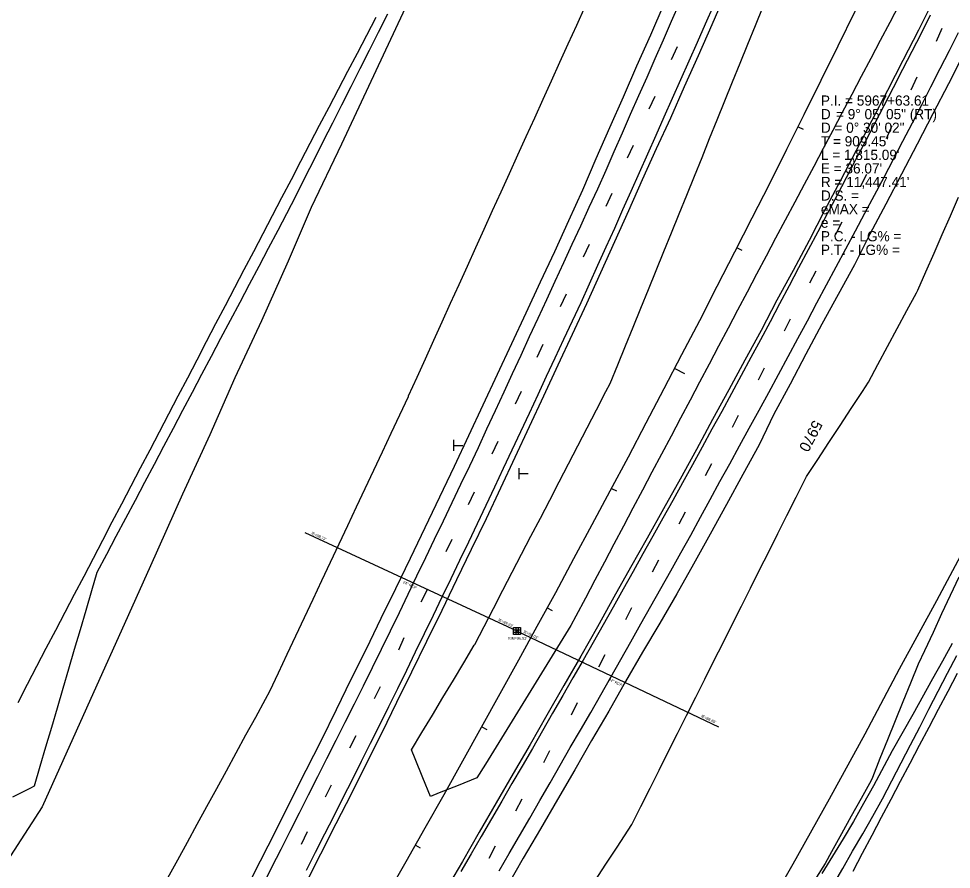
# Model space of a CAD drawing. Extents: x 2132221 to 2141942, y 535736 to 547298.
# Drawn here: x 2139563 to 2140250, y 543611 to 544238 of the extents above; entities that cross this region are included whole.
import ezdxf

# ---------------------------------------------------------------- set-up
doc = ezdxf.new("R2010")
doc.units = 0
for name, color, linetype in [('RD_EX_BldgApp', 7, 'Continuous'), ('RD_EX_DR_Inlet', 7, 'Continuous'), ('RD_EX_DR_Inlet_txCode', 7, 'Continuous'), ('RD_EX_DR_Pipe', 7, 'Continuous'), ('RD_EX_DR_Pipe_txCode', 7, 'Continuous'), ('RD_EX_Driveway', 7, 'Continuous'), ('RD_EX_Fence_Other', 7, 'Continuous'), ('RD_EX_Misc', 7, 'Continuous'), ('RD_EX_Road', 7, 'Continuous'), ('RD_EX_VEG', 7, 'Continuous'), ('RD_HC_Cl', 7, 'Continuous'), ('RD_HC_Data', 7, 'Continuous'), ('RD_HC_Data_Tic', 7, 'Continuous'), ('RD_HC_TX_Sta50', 7, 'Continuous'), ('TOPO_E_TLIML-Line', 7, 'Continuous')]:
    doc.layers.add(name, color=color, linetype=linetype)

msp = doc.modelspace()

# ---------------------------------------------------------------- linework, layer by layer
at = {"layer": 'RD_EX_BldgApp'}
for p, q in [((2139883.31, 543927.7), (2139883.31, 543923.58)), ((2139883.31, 543923.58), (2139883.31, 543919.47)), ((2139883.31, 543923.58), (2139890.17, 543923.58)), ((2139931.41, 543906.84), (2139931.41, 543902.72)), ((2139931.41, 543902.72), (2139931.41, 543898.6)), ((2139931.41, 543902.72), (2139938.27, 543902.72))]:
    msp.add_line(p, q, dxfattribs=at)
at = {"layer": 'RD_EX_DR_Inlet'}
for p, q in [((2139929.25, 543789.24), (2139929.25, 543784.24)), ((2139930.95, 543789.24), (2139930.95, 543784.24)), ((2139927.55, 543787.54), (2139932.55, 543787.54)), ((2139927.55, 543785.84), (2139932.55, 543785.84))]:
    msp.add_line(p, q, dxfattribs=at)
msp.add_lwpolyline([(2139927.55, 543784.24), (2139927.55, 543789.24), (2139932.55, 543789.24), (2139932.55, 543784.24)], close=True, dxfattribs=at)
at = {"layer": 'RD_EX_DR_Pipe'}
for q in [(2139773.88, 543859.09), (2140078.46, 543716.15)]:
    msp.add_line((2139930.09, 543786.68), q, dxfattribs=at)
at = {"layer": 'RD_EX_Driveway'}
for points in [[(2140250.79, 543777.62), (2140243.52, 543764.49), (2140236.26, 543751.36), (2140221.74, 543725.11), (2140206.45, 543698.27), (2140192.7, 543672.61), (2140185.44, 543659.49), (2140178.11, 543646.4), (2140170.32, 543633.58), (2140162.52, 543620.77), (2140154.73, 543607.95)], [(2140162.59, 543598.61), (2140170.07, 543611.61), (2140177.42, 543624.37), (2140184.84, 543637.25), (2140192.25, 543650.14), (2140199.53, 543663.1), (2140206.35, 543676.3), (2140213.17, 543689.51), (2140220, 543702.72), (2140226.82, 543715.92), (2140233.64, 543729.13), (2140240.47, 543742.34), (2140247.29, 543755.54), (2140254.11, 543768.75)]]:
    msp.add_lwpolyline(points, dxfattribs=at)
at = {"layer": 'RD_EX_Fence_Other'}
for points in [[(2140036.9, 544651.45), (2140013.35, 544603.46), (2139990.72, 544555.01), (2139970.35, 544511.31), (2139951.33, 544470.75), (2139928.94, 544422.41), (2139907.73, 544376.6), (2139887.27, 544332.67), (2139866.93, 544288.8), (2139845.9, 544242.19), (2139800.8, 544145.6), (2139778.31, 544098.97), (2139761.47, 544059.46), (2139741.78, 544015.43), (2139722.06, 543973.25), (2139703.54, 543931.28), (2139683.53, 543887.51), (2139659.89, 543834.83), (2139638.39, 543786.68), (2139620.42, 543746.85), (2139579.95, 543657.2), (2139556.74, 543620.94)], [(2139769.46, 542989.44), (2139792.81, 543030.29), (2139817.84, 543075.19), (2139841.76, 543117.2), (2139858.83, 543147.31), (2139881.84, 543188.22), (2139920.2, 543256.34), (2139947.4, 543301.84), (2139972.72, 543344.13), (2139997.22, 543384.87), (2140028.43, 543436.8), (2140054.25, 543479.64), (2140085.07, 543531.26), (2140112.36, 543577.99), (2140133.52, 543615.15), (2140160.47, 543662.97), (2140186.58, 543710.9), (2140211.9, 543758.94), (2140239.36, 543809.29), (2140263.01, 543853.34), (2140282.9, 543891.15)]]:
    msp.add_lwpolyline(points, dxfattribs=at)
at = {"layer": 'RD_EX_Misc'}
for p, q in [((2140243.22, 544230.86), (2140238.86, 544221.33)), ((2140043.86, 544208.11), (2140048.28, 544217.5)), ((2140224.72, 544194.91), (2140220.36, 544185.39)), ((2140027.43, 544171.69), (2140031.84, 544181.08)), ((2140206.36, 544159.11), (2140202, 544149.59)), ((2140011.44, 544135.52), (2140015.85, 544144.91)), ((2140187.62, 544123.13), (2140183.05, 544114.21)), ((2139995.81, 544100), (2140000.23, 544109.38)), ((2140169.45, 544088.04), (2140164.88, 544079.11)), ((2139978.98, 544062.49), (2139983.4, 544071.88)), ((2140150.19, 544052), (2140145.61, 544043.08)), ((2139962.19, 544026), (2139966.6, 544035.39)), ((2140131.42, 544016.67), (2140126.84, 544007.75)), ((2139944.98, 543988.68), (2139949.4, 543998.06)), ((2140112.25, 543980.6), (2140107.68, 543971.67)), ((2139928.97, 543954.26), (2139933.39, 543963.64)), ((2140093.13, 543945.56), (2140088.55, 543936.63)), ((2139911.7, 543917.24), (2139916.11, 543926.62)), ((2140073.38, 543909.96), (2140068.81, 543901.04)), ((2139894.26, 543879.95), (2139898.68, 543889.34)), ((2140053.97, 543874.35), (2140049.4, 543865.43)), ((2139877.77, 543845.25), (2139882.14, 543854.4)), ((2140034.34, 543839.04), (2140029.77, 543830.11)), ((2139859.51, 543808.18), (2139864.08, 543817.29)), ((2140014.46, 543803.87), (2140009.89, 543794.94)), ((2139842.97, 543772.77), (2139846.97, 543781.96)), ((2139994.71, 543769.04), (2139990.14, 543760.12)), ((2139824.89, 543736.84), (2139829.41, 543745.72)), ((2139974.49, 543733.67), (2139969.92, 543724.75)), ((2139806.77, 543700.56), (2139811.43, 543709.77)), ((2139954.09, 543698.47), (2139949.52, 543689.55)), ((2139788.82, 543664.59), (2139793.26, 543673.42)), ((2139933.61, 543662.79), (2139929.04, 543653.87)), ((2139771.1, 543629.58), (2139775.69, 543638.83)), ((2139913.86, 543628.06), (2139909.28, 543619.13))]:
    msp.add_line(p, q, dxfattribs=at)
for points in [[(2140049.76, 544249.8), (2140043.75, 544236.05), (2140037.71, 544222.32), (2140031.66, 544208.59), (2140025.62, 544194.87), (2140019.58, 544181.14), (2140013.53, 544167.41), (2140007.49, 544153.68), (2140001.45, 544139.95), (2139995.4, 544126.22), (2139989.36, 544112.49), (2139983.09, 544098.87), (2139976.8, 544085.25), (2139970.52, 544071.63), (2139964.23, 544058.01), (2139957.94, 544044.39), (2139951.65, 544030.77), (2139945.37, 544017.15), (2139939.08, 544003.54), (2139932.79, 543989.92), (2139926.51, 543976.3), (2139920.22, 543962.68), (2139913.93, 543949.06), (2139907.65, 543935.44), (2139901.36, 543921.82), (2139894.94, 543908.27), (2139888.46, 543894.74), (2139881.98, 543881.21), (2139875.5, 543867.68), (2139869.02, 543854.15), (2139862.54, 543840.62), (2139856.06, 543827.1), (2139849.58, 543813.57), (2139843.1, 543800.04), (2139836.57, 543786.54), (2139829.96, 543773.07), (2139823.35, 543759.61), (2139816.73, 543746.15), (2139809.97, 543732.76), (2139803.21, 543719.37), (2139796.44, 543705.98), (2139789.68, 543692.59), (2139782.92, 543679.2), (2139776.15, 543665.81), (2139769.39, 543652.42), (2139762.63, 543639.03), (2139755.87, 543625.64), (2139749.1, 543612.26), (2139742.34, 543598.87)], [(2139774.84, 543610.37), (2139781.62, 543623.75), (2139788.4, 543637.13), (2139795.19, 543650.51), (2139801.97, 543663.89), (2139808.75, 543677.27), (2139815.51, 543690.66), (2139822.17, 543704.1), (2139828.83, 543717.54), (2139835.49, 543730.98), (2139842.14, 543744.42), (2139848.72, 543757.9), (2139855.3, 543771.38), (2139861.88, 543784.86), (2139868.39, 543798.37), (2139874.91, 543811.89), (2139881.42, 543825.4), (2139887.94, 543838.91), (2139894.42, 543852.44), (2139900.84, 543865.99), (2139907.26, 543879.55), (2139913.68, 543893.1), (2139920.11, 543906.66), (2139926.53, 543920.21), (2139932.87, 543933.81), (2139939.2, 543947.41), (2139945.54, 543961), (2139951.87, 543974.6), (2139958.21, 543988.2), (2139964.54, 544001.79), (2139970.88, 544015.39), (2139977.21, 544028.99), (2139983.42, 544042.64), (2139989.64, 544056.29), (2139995.86, 544069.94), (2140002.02, 544083.62), (2140008.11, 544097.33), (2140014.2, 544111.03), (2140020.3, 544124.74), (2140026.39, 544138.45), (2140032.48, 544152.15), (2140038.57, 544165.86), (2140044.67, 544179.57), (2140050.76, 544193.27), (2140056.85, 544206.98), (2140062.94, 544220.69), (2140069.04, 544234.4), (2140075.02, 544248.15)], [(2140234.63, 544240.66), (2140227.83, 544227.29), (2140221.02, 544213.93), (2140214.22, 544200.56), (2140207.33, 544187.23), (2140200.4, 544173.93), (2140193.46, 544160.63), (2140186.52, 544147.34), (2140179.58, 544134.04), (2140172.64, 544120.74), (2140165.66, 544107.46), (2140158.65, 544094.2), (2140151.63, 544080.95), (2140144.61, 544067.69), (2140137.59, 544054.43), (2140130.58, 544041.17), (2140123.56, 544027.92), (2140116.51, 544014.67), (2140109.42, 544001.46), (2140102.32, 543988.25), (2140095.22, 543975.03), (2140088.12, 543961.82), (2140080.94, 543948.65), (2140073.73, 543935.49), (2140066.52, 543922.34), (2140059.31, 543909.19), (2140052.1, 543896.03), (2140044.8, 543882.93), (2140037.5, 543869.83), (2140030.2, 543856.72), (2140022.89, 543843.62), (2140015.59, 543830.52), (2140008.25, 543817.44), (2140000.86, 543804.38), (2139993.47, 543791.33), (2139986.08, 543778.28), (2139978.69, 543765.23), (2139971.23, 543752.21), (2139963.76, 543739.2), (2139956.29, 543726.2), (2139948.82, 543713.19), (2139941.34, 543700.18), (2139933.87, 543687.18), (2139926.33, 543674.21), (2139918.78, 543661.25), (2139911.24, 543648.29), (2139903.69, 543635.32), (2139896.14, 543622.36), (2139888.54, 543609.43)], [(2139916.81, 543609.82), (2139924.35, 543622.79), (2139931.88, 543635.76), (2139939.41, 543648.74), (2139946.92, 543661.72), (2139954.39, 543674.73), (2139961.86, 543687.74), (2139969.33, 543700.75), (2139976.85, 543713.72), (2139984.38, 543726.7), (2139991.85, 543739.7), (2139999.25, 543752.75), (2140006.65, 543765.8), (2140014.04, 543778.85), (2140021.39, 543791.93), (2140028.73, 543805.01), (2140036.08, 543818.09), (2140043.43, 543831.16), (2140050.77, 543844.24), (2140058.04, 543857.36), (2140065.24, 543870.52), (2140072.44, 543883.68), (2140079.64, 543896.84), (2140086.84, 543910), (2140094.03, 543923.16), (2140101.23, 543936.32), (2140108.43, 543949.48), (2140115.63, 543962.64), (2140122.82, 543975.81), (2140129.89, 543989.03), (2140136.97, 544002.26), (2140144.04, 544015.49), (2140151.12, 544028.71), (2140158.19, 544041.94), (2140165.27, 544055.17), (2140172.34, 544068.39), (2140179.42, 544081.62), (2140186.49, 544094.85), (2140193.57, 544108.07), (2140200.61, 544121.32), (2140207.54, 544134.62), (2140214.48, 544147.92), (2140221.41, 544161.22), (2140228.3, 544174.54), (2140235.11, 544187.91), (2140241.93, 544201.27), (2140248.74, 544214.64), (2140255.55, 544228)]]:
    msp.add_lwpolyline(points, dxfattribs=at)
at = {"layer": 'RD_EX_Road'}
for points in [[(2140083.37, 544256.55), (2140073.64, 544233.52), (2140063.48, 544210.67), (2140053.29, 544187.84), (2140043.25, 544164.88), (2140032.56, 544142.13), (2140022.3, 544119.33), (2140012.21, 544096.46), (2140001.83, 544073.71), (2139991.65, 544050.88), (2139981.19, 544027.91), (2139970.6, 544005.26), (2139960.02, 543982.62), (2139949.64, 543959.87), (2139938.98, 543937.26), (2139928.4, 543914.61), (2139917.83, 543891.95), (2139907.19, 543869.33), (2139896.2, 543846.87), (2139885.32, 543824.36), (2139874.52, 543801.81), (2139863.29, 543778.96), (2139852.33, 543756.49), (2139841.2, 543734.11), (2139830.34, 543711.59), (2139819.16, 543689.23), (2139807.95, 543666.88), (2139796.6, 543644.61), (2139785.32, 543622.2), (2139773.93, 543599.88)], [(2140038.3, 544248.93), (2140028.34, 544226), (2140018.22, 544203.14), (2140008.24, 544180.3), (2139998.13, 544157.63), (2139988.15, 544134.7), (2139978.21, 544111.76), (2139967.89, 544088.99), (2139957.55, 544066.23), (2139947.08, 544043.86), (2139936.66, 544021.13), (2139926.07, 543998.49), (2139915.39, 543975.89), (2139904.77, 543953.25), (2139894.23, 543930.58), (2139883.6, 543907.95), (2139872.9, 543885.36), (2139862.12, 543862.8), (2139851.33, 543840.25), (2139840.45, 543817.74), (2139829.74, 543795.86), (2139818.84, 543773.36), (2139807.68, 543750.99), (2139796.74, 543728.5), (2139785.66, 543706.09), (2139774.4, 543683.77), (2139763.18, 543661.43), (2139751.94, 543639.22), (2139740.73, 543616.96), (2139729.35, 543594.7)], [(2140236.99, 544252.01), (2140225.87, 544229.62), (2140214.47, 544207.37), (2140203, 544185.16), (2140191.5, 544163.05), (2140179.92, 544140.93), (2140168.38, 544118.75), (2140156.74, 544096.63), (2140145.27, 544074.56), (2140133.5, 544052.5), (2140121.63, 544030.5), (2140110.08, 544008.33), (2140098, 543986.44), (2140086.14, 543964.57), (2140074.21, 543942.61), (2140062.29, 543920.63), (2140050.31, 543898.69), (2140038.12, 543876.86), (2140026.06, 543855.28), (2140013.73, 543833.53), (2140001.44, 543811.77), (2139989.37, 543789.87), (2139977, 543768.14), (2139964.6, 543746.43), (2139952.11, 543724.78), (2139939.77, 543703.03), (2139927.28, 543681.65), (2139914.65, 543660.09), (2139902.15, 543638.44), (2139889.74, 543616.73), (2139877.11, 543595.16)], [(2140259.42, 544212.44), (2140248.02, 544190.19), (2140236.61, 544167.95), (2140224.98, 544145.67), (2140213.33, 544123.5), (2140201.77, 544101.33), (2140190.05, 544079.25), (2140178.7, 544056.75), (2140166.64, 544034.85), (2140154.78, 544012.84), (2140142.88, 543990.86), (2140131.26, 543968.72), (2140119.25, 543946.57), (2140108.44, 543924), (2140096.5, 543902.03), (2140084.52, 543880.09), (2140072.45, 543858.19), (2140060.05, 543835.99), (2140047.73, 543814.23), (2140035.39, 543792.49), (2140022.59, 543771.01), (2140010.02, 543749.4), (2139997.65, 543727.68), (2139985.02, 543706.1), (2139972.68, 543684.36), (2139959.88, 543662.48), (2139947.26, 543640.88), (2139934.66, 543619.29), (2139922.22, 543597.6)]]:
    msp.add_lwpolyline(points, dxfattribs=at)
at = {"layer": 'RD_EX_VEG'}
for points in [[(2139672.76, 543604.76), (2139679.95, 543617.92), (2139687.14, 543631.09), (2139694.32, 543644.25), (2139701.51, 543657.42), (2139708.7, 543670.58), (2139715.89, 543683.75), (2139723.08, 543696.91), (2139730.27, 543710.08), (2139737.46, 543723.24), (2139744.65, 543736.41), (2139747.93, 543742.42), (2139754.31, 543756), (2139760.68, 543769.57), (2139767.06, 543783.15), (2139773.44, 543796.73), (2139779.82, 543810.3), (2139786.19, 543823.88), (2139792.57, 543837.46), (2139798.95, 543851.03), (2139805.32, 543864.61), (2139811.7, 543878.19), (2139818.08, 543891.76), (2139824.46, 543905.34), (2139830.83, 543918.92), (2139837.21, 543932.5), (2139843.59, 543946.07), (2139849.96, 543959.65), (2139850.18, 543960.1), (2139856.37, 543973.77), (2139862.56, 543987.43), (2139868.75, 544001.09), (2139874.94, 544014.75), (2139881.13, 544028.42), (2139887.33, 544042.08), (2139893.52, 544055.74), (2139899.71, 544069.4), (2139905.9, 544083.07), (2139912.09, 544096.73), (2139918.28, 544110.39), (2139924.47, 544124.05), (2139930.67, 544137.72), (2139936.86, 544151.38), (2139943.05, 544165.04), (2139949.24, 544178.7), (2139955.43, 544192.37), (2139961.62, 544206.03), (2139967.81, 544219.69), (2139974.01, 544233.35), (2139980.2, 544247.02)], [(2140211.82, 544248.61), (2140204.81, 544235.35), (2140197.8, 544222.09), (2140190.79, 544208.82), (2140183.77, 544195.56), (2140176.76, 544182.3), (2140169.75, 544169.04), (2140162.74, 544155.78), (2140155.73, 544142.52), (2140148.72, 544129.26), (2140141.71, 544116), (2140134.69, 544102.74), (2140127.68, 544089.48), (2140120.67, 544076.22), (2140113.66, 544062.96), (2140106.65, 544049.7), (2140099.64, 544036.44), (2140092.63, 544023.18), (2140085.61, 544009.92), (2140078.6, 543996.66), (2140071.59, 543983.4), (2140064.58, 543970.14), (2140057.57, 543956.88), (2140050.56, 543943.62), (2140043.55, 543930.36), (2140036.53, 543917.09), (2140029.52, 543903.83), (2140022.51, 543890.57), (2140015.5, 543877.31), (2140008.49, 543864.05), (2140001.48, 543850.79), (2139994.47, 543837.53), (2139987.45, 543824.27), (2139980.44, 543811.01), (2139973.43, 543797.75), (2139969.69, 543790.68), (2139961.82, 543777.91), (2139953.94, 543765.15), (2139946.07, 543752.38), (2139938.19, 543739.62), (2139930.31, 543726.85), (2139922.44, 543714.08), (2139914.56, 543701.32), (2139906.69, 543688.55), (2139900.52, 543678.56), (2139886.62, 543672.93), (2139872.72, 543667.3), (2139866.17, 543664.65), (2139860.54, 543678.55), (2139854.91, 543692.46), (2139852.26, 543699.01), (2139859.97, 543711.87), (2139867.69, 543724.73), (2139875.4, 543737.6), (2139883.11, 543750.46), (2139890.83, 543763.33), (2139898.54, 543776.19), (2139898.89, 543776.77), (2139905.8, 543790.08), (2139912.71, 543803.39), (2139919.61, 543816.71), (2139926.52, 543830.02), (2139933.43, 543843.34), (2139940.34, 543856.65), (2139947.25, 543869.97), (2139954.16, 543883.28), (2139961.07, 543896.59), (2139967.98, 543909.91), (2139974.88, 543923.22), (2139981.79, 543936.54), (2139988.7, 543949.85), (2139995.61, 543963.17), (2139998.68, 543969.08), (2140004.32, 543982.98), (2140009.96, 543996.88), (2140015.61, 544010.78), (2140021.25, 544024.68), (2140026.89, 544038.57), (2140032.53, 544052.47), (2140038.17, 544066.37), (2140043.81, 544080.27), (2140049.46, 544094.17), (2140055.1, 544108.07), (2140060.74, 544121.97), (2140066.38, 544135.86), (2140072.02, 544149.76), (2140077.66, 544163.66), (2140083.31, 544177.56), (2140088.95, 544191.46), (2140094.59, 544205.36), (2140100.23, 544219.26), (2140105.87, 544233.15), (2140111.51, 544247.05)], [(2139558.33, 543664.41), (2139571.7, 543671.21), (2139574.4, 543672.58), (2139578.63, 543686.97), (2139582.86, 543701.37), (2139587.08, 543715.76), (2139591.31, 543730.15), (2139595.53, 543744.54), (2139599.76, 543758.93), (2139603.99, 543773.33), (2139608.21, 543787.72), (2139612.44, 543802.11), (2139616.66, 543816.5), (2139620.68, 543830.17), (2139627.69, 543843.43), (2139634.7, 543856.69), (2139641.72, 543869.95), (2139648.73, 543883.21), (2139655.74, 543896.47), (2139662.76, 543909.73), (2139669.77, 543922.99), (2139676.79, 543936.25), (2139683.8, 543949.51), (2139690.81, 543962.77), (2139697.83, 543976.03), (2139704.84, 543989.29), (2139711.85, 544002.54), (2139718.87, 544015.8), (2139725.88, 544029.06), (2139732.89, 544042.32), (2139739.91, 544055.58), (2139746.92, 544068.84), (2139753.93, 544082.1), (2139760.43, 544094.39), (2139767.19, 544107.78), (2139773.96, 544121.17), (2139780.72, 544134.56), (2139787.48, 544147.95), (2139794.24, 544161.34), (2139801, 544174.73), (2139807.76, 544188.12), (2139814.52, 544201.51), (2139821.28, 544214.9), (2139828.04, 544228.29), (2139834.8, 544241.68)], [(2139987.35, 543602.33), (2139995.57, 543614.88), (2140003.79, 543627.42), (2140012.01, 543639.97), (2140014.66, 543644.02), (2140021.39, 543657.43), (2140028.11, 543670.84), (2140034.84, 543684.25), (2140041.56, 543697.65), (2140048.29, 543711.06), (2140055.01, 543724.47), (2140061.74, 543737.88), (2140068.46, 543751.29), (2140075.19, 543764.69), (2140081.91, 543778.1), (2140088.64, 543791.51), (2140095.37, 543804.92), (2140102.09, 543818.33), (2140108.82, 543831.73), (2140115.54, 543845.14), (2140122.27, 543858.55), (2140128.99, 543871.96), (2140135.72, 543885.36), (2140142.44, 543898.77), (2140143.42, 543900.72), (2140151.66, 543913.25), (2140159.89, 543925.79), (2140168.13, 543938.33), (2140176.37, 543950.86), (2140184.6, 543963.4), (2140188.98, 543970.05), (2140196.08, 543983.26), (2140203.18, 543996.48), (2140210.29, 544009.69), (2140217.39, 544022.9), (2140224.49, 544036.11), (2140225.44, 544037.86), (2140231.43, 544051.61), (2140237.43, 544065.36), (2140243.42, 544079.11), (2140249.42, 544092.86), (2140255.41, 544106.61)], [(2140255.68, 543826.5), (2140249.34, 543812.91), (2140243, 543799.32), (2140236.66, 543785.72), (2140230.31, 543772.13), (2140225.7, 543762.23), (2140220.07, 543748.32), (2140214.44, 543734.42), (2140208.81, 543720.51), (2140203.18, 543706.61), (2140197.55, 543692.7), (2140191.93, 543678.8), (2140190.97, 543676.45), (2140183.7, 543663.33), (2140176.43, 543650.21), (2140169.16, 543637.09), (2140161.88, 543623.97), (2140157.05, 543615.25), (2140148.99, 543602.6)]]:
    msp.add_lwpolyline(points, dxfattribs=at)
at = {"layer": 'RD_HC_Cl'}
msp.add_arc((2129895.56, 549272.3), 11447.41, 329.115721, 338.200487, dxfattribs=at)
at = {"layer": 'RD_HC_Data_Tic'}
for p, q in [((2140137.24, 544158.49), (2140140.82, 544156.71)), ((2140092.18, 544069.22), (2140095.75, 544067.4)), ((2140046.34, 543980.35), (2140053.44, 543976.65)), ((2139999.73, 543891.88), (2140003.26, 543890)), ((2139952.34, 543803.82), (2139955.85, 543801.91)), ((2139904.19, 543716.18), (2139907.68, 543714.23)), ((2139855.27, 543628.96), (2139858.75, 543626.99))]:
    msp.add_line(p, q, dxfattribs=at)
at = {"layer": 'TOPO_E_TLIML-Line'}
for points in [[(2139826.01, 544239.08), (2139819.07, 544225.79), (2139812.12, 544212.5), (2139805.17, 544199.2), (2139798.23, 544185.91), (2139791.28, 544172.61), (2139784.33, 544159.32), (2139777.39, 544146.02), (2139770.44, 544132.73), (2139763.49, 544119.43), (2139756.55, 544106.14), (2139749.6, 544092.84), (2139742.66, 544079.55), (2139735.71, 544066.26), (2139728.76, 544052.96), (2139721.82, 544039.67), (2139714.87, 544026.37), (2139707.92, 544013.08), (2139700.98, 543999.78), (2139694.03, 543986.49), (2139687.08, 543973.19), (2139680.14, 543959.9), (2139673.19, 543946.6), (2139666.24, 543933.31), (2139659.3, 543920.02), (2139652.35, 543906.72), (2139645.4, 543893.43), (2139638.46, 543880.13), (2139631.51, 543866.84), (2139624.56, 543853.54), (2139617.62, 543840.25), (2139610.67, 543826.95), (2139603.72, 543813.66), (2139596.78, 543800.36), (2139589.83, 543787.07), (2139582.88, 543773.77), (2139575.94, 543760.48), (2139568.99, 543747.19), (2139562.05, 543733.89)], [(2140177.77, 543609.63), (2140184.77, 543622.9), (2140191.77, 543636.16), (2140198.77, 543649.43), (2140205.77, 543662.69), (2140212.78, 543675.96), (2140219.78, 543689.23), (2140226.78, 543702.49), (2140233.78, 543715.76), (2140240.78, 543729.02), (2140247.78, 543742.29), (2140254.78, 543755.55)]]:
    msp.add_lwpolyline(points, dxfattribs=at)

# ---------------------------------------------------------------- texts
at = {"layer": 'RD_EX_DR_Inlet_txCode'}
for s, rotation, p in [("IE=88.73'", 335.13145, (2139778.25, 543858.16)), ("IE=89.93'", 335.13145, (2139915.97, 543794.33)), ("IE=90.03'", 334.57521, (2139934.58, 543785.65)), ("IE=88.85'", 334.57521, (2140065.59, 543723.38))]:
    msp.add_text(s, height=2, rotation=rotation, dxfattribs=at).set_placement(p)
msp.add_text("RIM=96.53'", height=2, dxfattribs=at).set_placement((2139923.33, 543780.38))
at = {"layer": 'RD_EX_DR_Pipe_txCode'}
for rotation, p in [(335.13145, (2139845.75, 543822.06)), (334.57521, (2139997.41, 543750.31))]:
    msp.add_text('24" RCP', height=2, rotation=rotation, dxfattribs=at).set_placement(p)
at = {"layer": 'RD_HC_Data'}
for s, p in [('P.I. = 5967+63.61', (2140154, 544174)), ('D', (2140154, 544164)), ('    = 9%%d 05\' 05" (RT)', (2140154, 544164)), ('D = 0%%d 30\' 02"', (2140154, 544154)), ("T = 909.45'", (2140154, 544144)), ("L = 1,815.09'", (2140154, 544134)), ("E = 36.07'", (2140154, 544124)), ("R = 11,447.41'", (2140154, 544114)), ('D.S. = ', (2140154, 544104)), ('eMAX = ', (2140154, 544094)), ('e = ', (2140154, 544084)), ('P.C. - LG% = ', (2140154, 544074)), ('P.T. - LG% = ', (2140154, 544064))]:
    msp.add_text(s, height=7.5, dxfattribs=at).set_placement(p)
at = {"layer": 'RD_HC_TX_Sta50'}
msp.add_text('5970', height=8, rotation=242.4654, dxfattribs=at).set_placement((2140148.55, 543942.77))

doc.saveas('drawing.dxf')
